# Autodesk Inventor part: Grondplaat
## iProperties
Created: 2007-06
Part Number: Grondplaat
Material: Steel
Document SubType Name: Modeling
Designer: Phil Trethewie
Author: Phil Trethewie
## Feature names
1. Extrusion1
2. Fillet1
